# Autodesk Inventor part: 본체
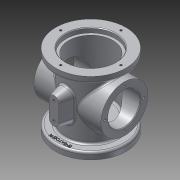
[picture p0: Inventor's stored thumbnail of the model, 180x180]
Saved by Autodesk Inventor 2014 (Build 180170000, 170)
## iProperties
Created: 2018-02
Part Number: 본체
Material: 알루미늄 6061
Document SubType Name: Modeling
Designer: kb542
Density: 2.71 g/cm^3
Appearance: 알루미늄 - 평지
Author: kb542
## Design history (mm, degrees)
sketch "스케치1"
  geometry: L1 (0, 0)-(0, 108); L2 (-33, 0)-(-52.5, 0); L3 (-52.5, 0)-(-52.5, 10); L4 (-52.5, 10)-(-38, 10); L5 (-38, 10)-(-38, 98); L6 (-38, 98)-(-52.5, 98); L7 (-52.5, 98)-(-52.5, 108); L8 (-52.5, 108)-(-33, 108); L9 (-33, 108)-(-33, 0)
  constraints: 18 end point, 4 parallel, 4 perpendicular, 2 horizontal alignment, 1 vertical
  dimensions: "d0" = 105 diameter of L3 L1; "d1" = 66 diameter of L9 L1; "d2" = 76 diameter of L5 L1; "d3" = 105 diameter of L7 L1; "d4" = 10 distance between parallel lines of L2 L4; "d5" = 10 distance between parallel lines of L6 L8; "d6" = 108 distance between parallel lines of L2 L8
revolve "회전1" sketch "스케치1" stored, may be unused: angle "d7" = 90 deg
node "작업 평면2"
  node "작업 평면1"
sketch "스케치3"
  geometry: L1 (-38, -44)-(-38, 44) reference; L2 (52.5, 44)-(-52.5, 44) reference; C1 r 35 at (0, 0); 3 further points
  constraints: 2 midpoint, 1 centre point, 1 horizontal alignment, 1 vertical alignment
  dimensions: "d10" = 70 diameter of C1
extrude "돌출1" join sketch "스케치3" stored distance "d11" = 10; taper "d12" = 0 deg
sketch "스케치4"
  geometry: C1 r 35 at (0, 0) reference; C2 r 24 at (0, 0); 1 further point
  constraints: 1 centre point, 1 coincident
  dimensions: "d13" = 48 diameter of C2
extrude "돌출2" cut sketch "스케치4" stored distance "d14" = 10; taper "d15" = 0 deg
sketch "스케치5"
  geometry: L1 (108, 33)-(0, 33) reference; L2 (108, -33)-(0, -33) reference; L3 (30, 50)-(30, 33) reference; L4 (30, -33)-(30, -50) reference; L5 (30, 33)-(30, 0); L6 (30, 0)-(0, 0); L7 (0, 0)-(0, 33)
  constraints: 6 end point, 2 perpendicular, 1 collinear, 1 vertical
revolve "회전2" sketch "스케치5" stored, may be unused: angle "d17" = 90 deg
sketch "스케치6"
  geometry: L1 (0, -52.5)-(0, 52.5) reference; L2 (30, 33)-(30, -33) reference; L3 (30, 50)-(30, 33) reference; L4 (30, 33)-(22, 33); L5 (22, 33)-(22, 5); L6 (22, 5)-(16, 5); L7 (16, 5)-(16, 34); L8 (16, 34)-(0, 34); L9 (0, 0)-(30, 0); L10 (108, -33)-(108, 33) reference
  constraints: 12 end point, 3 perpendicular, 2 parallel, 1 midpoint, 1 point on line
  dimensions: "d18" = 16 distance between parallel lines of L1 L7; "d19" = 5 distance between parallel lines of L9 L6; "d20" = 86 distance between parallel lines of L5 L10; "d21" = 68 diameter of L8 L9
revolve "회전3" sketch "스케치6" stored, may be unused: angle "d22" = 90 deg
sketch "스케치7"
  geometry: L1 (108, 33)-(22, 33) reference; L2 (108, -33)-(22, -33) reference; L3 (108, -33)-(108, 33) reference; L4 (108, 0)-(101, 0); L5 (101, 0)-(101, 33); 1 further point
  constraints: 4 end point, 2 perpendicular, 1 midpoint, 1 point on line
  dimensions: "d23" = 7 distance of L4.start L4.end
revolve "회전4" sketch "스케치7" stored, may be unused: angle "d24" = 90 deg
sketch "스케치8"
  geometry: L1 (108, -52.5)-(108, 52.5) reference; L2 (101, -33)-(101, 33) reference; L3 (101, 0)-(108, 0); L4 (101, 37)-(108, 37); L5 (101, 33)-(101, 37); 1 further point
  constraints: 6 end point, 2 midpoint, 2 perpendicular, 2 point on line
  dimensions: "d25" = 74 diameter of L4 L3
revolve "회전5" sketch "스케치8" stored, may be unused: angle "d26" = 90 deg
sketch "스케치9" dims "d27" = 90
  geometry: C1 r 37 at (0, 0) reference; C2 r 52.5 at (0, 0) reference; 2 further points
  constraints: 2 vertical alignment, 1 coincident, 2 other
hole "구멍1" sketch "스케치9" at (0, 45) diameter "d28" = 3.242; stored, may be unused: countersink angle "d32" = 90 deg, drill point angle "d34" = 118 deg; dims "d29" = 4, "d30" = 4, "d31" = 2, "d33" = 6
node "작업 평면3"
sketch "스케치10" dims "d38" = 58
  geometry: C1 r 24 at (0, 0) reference; C2 r 35 at (0, 0) reference; 3 further points
  constraints: 2 vertical alignment, 1 coincident, 2 other
hole "구멍2" sketch "스케치10" at (0, 29) diameter "d39" = 3.242; stored, may be unused: countersink angle "d43" = 90 deg, drill point angle "d45" = 118 deg; dims "d40" = 4, "d41" = 4, "d42" = 2, "d44" = 6
node "작업 평면4"
sketch "스케치12"
  geometry: L1 (67, 0)-(41, 0); L2 (67, 7)-(41, 7); L3 (41, -7)-(67, -7); L4 (19, -50)-(89, -50) reference; A1 r 7 centre (67, 0) between (67, -7) and (67, 7); A2 r 7 centre (41, 0) between (41, 7) and (41, -7); 3 further points
  constraints: 8 end point, 4 point on circle, 4 tangent, 2 centre point, 2 midpoint, 1 horizontal, 1 horizontal alignment, 1 parallel, 1 vertical alignment
  dimensions: "d50" = 7 radius of A1; "d51" = 40 dimension on A2 A1
extrude "돌출3" join sketch "스케치12" stored distance "d52" = 10; taper "d53" = 15 deg
sketch "스케치15"
  geometry: A1 r 7 centre (0, 41) between (-7, 41) and (7, 41) reference; A2 r 7 centre (0, 67) between (7, 67) and (-7, 67) reference; 3 further points
  constraints: 2 coincident
hole "구멍3" sketch "스케치15" at (0, 67), (0, 41) diameter "d54" = 4.134; stored, may be unused: countersink angle "d58" = 90 deg, drill point angle "d60" = 118 deg; dims "d55" = 6, "d56" = 4, "d57" = 2, "d59" = 8
sketch "스케치16"
  geometry: L1 (0, 0)-(43, 0); C1 r 38 at (0, 0) reference; 1 further point
  constraints: 2 end point, 1 coincident, 1 horizontal, 1 other
  dimensions: "d61" = 43 distance of L1.start L1.end
extrude "돌출4" join sketch "스케치16" distance "d62" = 0.5; taper "d63" = 0 deg
chamfer "모따기1" distance "d64" = 1; stored, may be unused: second distance "d65" = 2, angle "d66" = 45 deg
fillet "모깎기1" dims "d67" = 3
fillet "모깎기2" dims "d68" = 3
chamfer "모따기2" distance "d69" = 1; stored, may be unused: second distance "d70" = 2, angle "d71" = 45 deg
fillet "모깎기3" dims "d72" = 3
node "솔리드1"
mirror "대칭1"
pattern_circular "원형 패턴1" dims angle "d36" = 360 deg
pattern_circular "원형 패턴2" dims angle "d47" = 360 deg
mirror "대칭3"
other parameters: "d9" = 12, "d49" = 55
